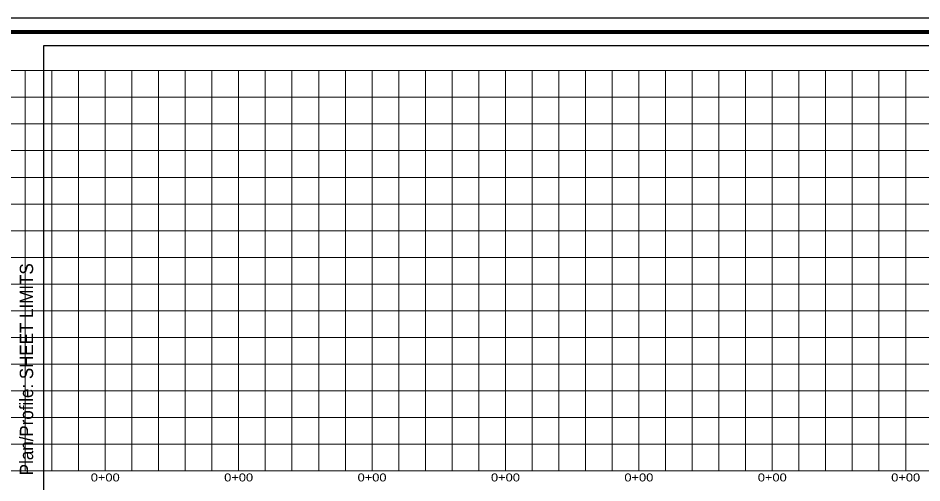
# Model space of a CAD drawing. Extents: x 2246932 to 2264252, y 7095151 to 7098651.
# Drawn here: x 2252265 to 2255652, y 7096909 to 7098651 of the extents above; entities that cross this region are included whole.
import ezdxf
from ezdxf.enums import TextEntityAlignment as Align

# ---------------------------------------------------------------- set-up
doc = ezdxf.new("R2010")
doc.units = 0
doc.header["$LTSCALE"] = 12
for name, color, linetype, lineweight in [('1', 7, 'Continuous', 80), ('62', 7, 'Continuous', 13), ('63', 7, 'Continuous', 25)]:
    doc.layers.add(name, color=color, linetype=linetype, lineweight=lineweight)
doc.layers.add('22', color=7, linetype='Continuous')

msp = doc.modelspace()

# ---------------------------------------------------------------- linework, layer by layer
at = {"layer": '1'}
msp.add_line((2264052.09, 7098598.35), (2247157.09, 7098598.35), dxfattribs=at)
at = {"layer": '1', "lineweight": 25}
msp.add_lwpolyline([(2264104.59, 7095150.85), (2264104.59, 7098650.85), (2247104.59, 7098650.85), (2247104.59, 7095150.85)], dxfattribs=at)
at = {"layer": '62'}
for p, q in [((2247941.45, 7098454.14), (2263241.45, 7098454.14)), ((2252291.45, 7098454.14), (2252291.45, 7096954.14)), ((2252391.45, 7098454.14), (2252391.45, 7096954.14)), ((2252491.45, 7098454.14), (2252491.45, 7096954.14)), ((2252591.45, 7098454.14), (2252591.45, 7096954.14)), ((2252691.45, 7098454.14), (2252691.45, 7096954.14)), ((2252791.45, 7098454.14), (2252791.45, 7096954.14)), ((2252891.45, 7098454.14), (2252891.45, 7096954.14)), ((2252991.45, 7098454.14), (2252991.45, 7096954.14)), ((2253091.45, 7098454.14), (2253091.45, 7096954.14)), ((2253191.45, 7098454.14), (2253191.45, 7096954.14)), ((2253291.45, 7098454.14), (2253291.45, 7096954.14)), ((2253391.45, 7098454.14), (2253391.45, 7096954.14)), ((2253491.45, 7098454.14), (2253491.45, 7096954.14)), ((2253591.45, 7098454.14), (2253591.45, 7096954.14)), ((2253691.45, 7098454.14), (2253691.45, 7096954.14)), ((2253791.45, 7098454.14), (2253791.45, 7096954.14)), ((2253891.45, 7098454.14), (2253891.45, 7096954.14)), ((2253991.45, 7098454.14), (2253991.45, 7096954.14)), ((2254091.45, 7098454.14), (2254091.45, 7096954.14)), ((2254191.45, 7098454.14), (2254191.45, 7096954.14)), ((2254291.45, 7098454.14), (2254291.45, 7096954.14)), ((2254391.45, 7098454.14), (2254391.45, 7096954.14)), ((2254491.45, 7098454.14), (2254491.45, 7096954.14)), ((2254591.45, 7098454.14), (2254591.45, 7096954.14)), ((2254691.45, 7098454.14), (2254691.45, 7096954.14)), ((2254791.45, 7098454.14), (2254791.45, 7096954.14)), ((2254891.45, 7098454.14), (2254891.45, 7096954.14)), ((2254991.45, 7098454.14), (2254991.45, 7096954.14)), ((2255091.45, 7098454.14), (2255091.45, 7096954.14)), ((2255191.45, 7098454.14), (2255191.45, 7096954.14)), ((2255291.45, 7098454.14), (2255291.45, 7096954.14)), ((2255391.45, 7098454.14), (2255391.45, 7096954.14)), ((2255491.45, 7098454.14), (2255491.45, 7096954.14)), ((2255591.45, 7098454.14), (2255591.45, 7096954.14)), ((2259241.45, 7097654.14), (2249441.45, 7097654.14)), ((2252291.45, 7097654.14), (2252291.45, 7096954.14)), ((2252391.45, 7097654.14), (2252391.45, 7096954.14)), ((2263241.45, 7096954.14), (2247941.45, 7096954.14))]:
    msp.add_line(p, q, dxfattribs=at)
for points in [[(2248091.45, 7098354.14), (2263091.45, 7098354.14), (2263241.45, 7098354.14)], [(2248091.45, 7098254.14), (2263091.45, 7098254.14), (2263241.45, 7098254.14)], [(2248091.45, 7098154.14), (2263091.45, 7098154.14), (2263241.45, 7098154.14)], [(2248091.45, 7098054.14), (2263091.45, 7098054.14), (2263241.45, 7098054.14)], [(2248091.45, 7097954.14), (2263091.45, 7097954.14), (2263241.45, 7097954.14)], [(2248091.45, 7097854.14), (2263091.45, 7097854.14), (2263241.45, 7097854.14)], [(2248091.45, 7097754.14), (2263091.45, 7097754.14), (2263241.45, 7097754.14)], [(2248091.45, 7097654.14), (2263091.45, 7097654.14), (2263241.45, 7097654.14)], [(2248091.45, 7097554.14), (2263091.45, 7097554.14), (2263241.45, 7097554.14)], [(2248091.45, 7097454.14), (2263091.45, 7097454.14), (2263241.45, 7097454.14)], [(2248091.45, 7097354.14), (2263091.45, 7097354.14), (2263241.45, 7097354.14)], [(2248091.45, 7097254.14), (2263091.45, 7097254.14), (2263241.45, 7097254.14)], [(2248091.45, 7097154.14), (2263091.45, 7097154.14), (2263241.45, 7097154.14)], [(2248091.45, 7097054.14), (2263091.45, 7097054.14), (2263241.45, 7097054.14)]]:
    msp.add_lwpolyline(points, dxfattribs=at)
at = {"layer": '63'}
msp.add_lwpolyline([(2252360.97, 7098548.06), (2262360.97, 7098548.06), (2262360.97, 7096798.06), (2252360.97, 7096798.06)], close=True, dxfattribs=at)

# ---------------------------------------------------------------- texts
at = {"layer": '22', "width": 1.2}
for p in [(2252591.45, 7096914.74), (2253091.45, 7096914.74), (2253591.45, 7096914.74), (2254091.45, 7096914.74), (2254591.45, 7096914.74), (2255091.45, 7096914.74), (2255591.45, 7096914.74)]:
    msp.add_text('0+00', height=30, dxfattribs=at).set_placement(p, align=Align.CENTER)
at = {"layer": '63', "width": 0.95}
msp.add_text('Plan/Profile: SHEET LIMITS', height=50, rotation=90, dxfattribs=at).set_placement((2252321.29, 7097335.05), align=Align.CENTER)

doc.saveas('drawing.dxf')
